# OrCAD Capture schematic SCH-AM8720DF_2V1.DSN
size Custom
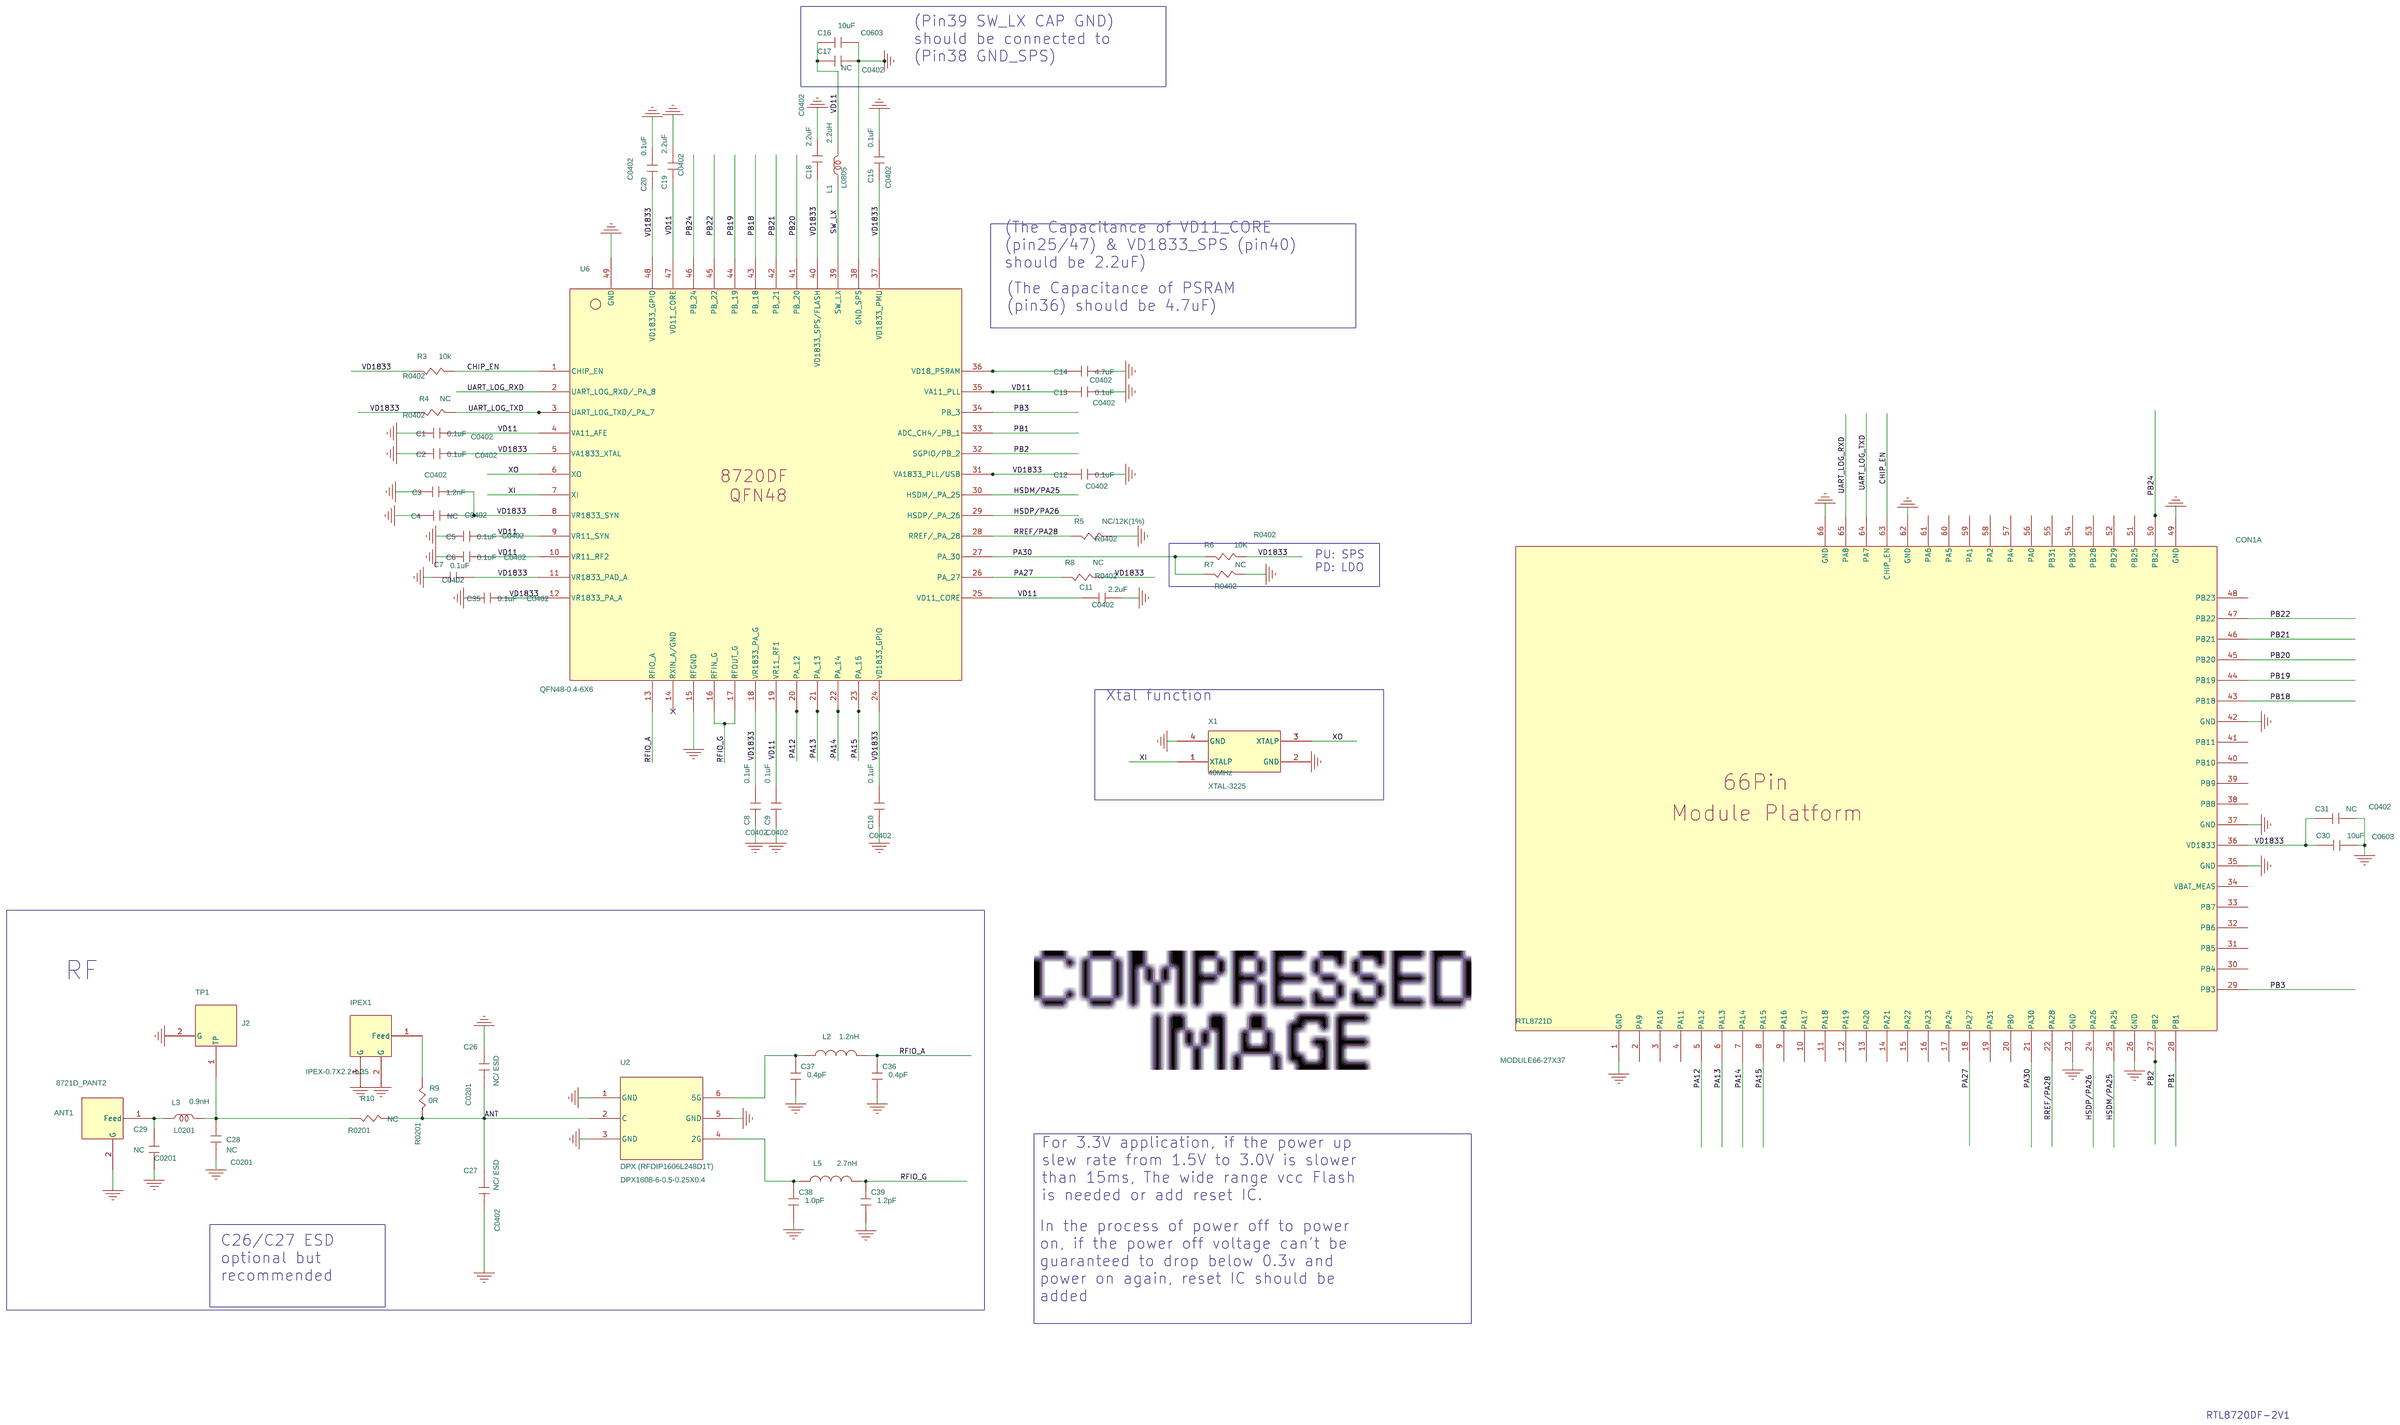
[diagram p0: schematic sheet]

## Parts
ANT1  TP  [8721D_PANT2]
C1  0.1uF  [C0402]
C2  0.1uF  [C0402]
C3  1.2nF  [C0402]
C4  NC  [C0402]
C5  0.1uF  [C0402]
C6  0.1uF  [C0402]
C7  0.1uF  [C0402]
C8  0.1uF  [C0402]
C9  0.1uF  [C0402]
C10  0.1uF  [C0402]
C11  2.2uF  [C0402]
C12  0.1uF  [C0402]
C13  0.1uF  [C0402]
C14  4.7uF  [C0402]
C15  0.1uF  [C0402]
C16  10uF  [C0603]
C17  NC  [C0402]
C18  2.2uF  [C0402]
C19  2.2uF  [C0402]
C20  0.1uF  [C0402]
C26  NC/ ESD  [C0201]
C27  NC/ ESD  [C0402]
C28  NC  [C0201]
C29  NC  [C0201]
C30  10uF  [C0603]
C31  NC  [C0402]
C35  0.1uF  [C0402]
C36  0.4pF  [C0402]
C37  0.4pF  [C0402]
C38  1.0pF  [C0402]
C39  1.2pF  [C0402]
CON1  RTL8721D  [MODULE66-27X37]  (section A)
IPEX1  TP  [IPEX-0.7X2.2-1.35]
L1  2.2uH  [L0805]
L2  1.2nH  [L0402]
L3  0.9nH  [L0201]
L5  2.7nH  [L0402]
R3  10k  [R0402]
R4  NC  [R0402]
R5  NC/12K(1%)  [R0402]
R6  10K  [R0402]
R7  NC  [R0402]
R8  NC  [R0402]
R9  0R  [R0201]
R10  NC  [R0201]
TP1  TP  [J2]
U2  DPX (RFDIP1606L248D1T)  [DPX1608-6-0.5-0.25X0.4]
U6  RL5760_001  [QFN48-0.4-6X6]
X1  40MHz  [XTAL-3225]

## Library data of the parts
ANT1 = TP_2
C1-C20 C26-C31 C35-C39 = C_402
CON1 = 8723BS_73
IPEX1 = TP_3
L1 L3 = L0402_1.7NH_ACX
L2 L5 = INDUCTOR: BRCMPN: RokuPN Checked; OPTION: RF; PartDesc: Inductor, 2.0nH, 5%, 0402, OBD; ROKUPN: 1372000247
R3-R10 = R0402_1.06K_WALSIN
TP1 = TP_4
U2 = 9346_19
U6 = RL5760_45
X1 = 9346_0

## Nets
GND: ANT1.2(G) C1.1 C2.1 C3.1 C4.2 C5.2 C6.2 C7.1 C8.2 C9.2 C10.2 C11.2 C12.2 C13.2 C14.2 C15.2 C16.1 C17.1 C18.2 C19.2 C20.2 C26.1 C27.2 C28.1 C29.1 C30.2 C31.1 C35.1 C36.2 C37.2 C38.2 C39.2 CON1.1(GND) CON1.23(GND) CON1.26(GND) CON1.35(GND) CON1.37(GND) CON1.42(GND) CON1.49(GND) CON1.62(GND) CON1.66(GND) IPEX1.2(G) IPEX1.3(G) R5.1 R7.2 TP1.2(G) U2.1(GND) U2.3(GND) U2.5(GND) U6.15(RFGND) U6.38(GND_SPS) U6.49(GND) X1.2(GND) X1.4(GND)
ANT: C26.2 C27.1 R9.1 R10.1 U2.2(C)
CHIP_EN: CON1.63(CHIP_EN) R3.1 U6.1(CHIP_EN)
HSDM/PA25: CON1.25(PA25) U6.30(HSDM/_PA_25)
HSDP/PA26: CON1.24(PA26) U6.29(HSDP/_PA_26)
PA12: CON1.5(PA12) U6.20(PA_12)
PA13: CON1.6(PA13) U6.21(PA_13)
PA14: CON1.7(PA14) U6.22(PA_14)
PA15: CON1.8(PA15) U6.23(PA_15)
PA27: CON1.18(PA27) R8.2 U6.26(PA_27)
PA30: CON1.21(PA30) R6.2 R7.1 U6.27(PA_30)
PB1: CON1.28(PB1) U6.33(ADC_CH4/_PB_1)
PB2: CON1.27(PB2) U6.32(SGPIO/PB_2)
PB3: CON1.29(PB3) U6.34(PB_3)
PB18: CON1.43(PB18) U6.43(PB_18)
PB19: CON1.44(PB19) U6.44(PB_19)
PB20: CON1.45(PB20) U6.41(PB_20)
PB21: CON1.46(PB21) U6.42(PB_21)
PB22: CON1.47(PB22) U6.45(PB_22)
PB24: CON1.50(PB24) U6.46(PB_24)
RFIO_A: C36.1 L2.2 U6.13(RFIO_A)
RFIO_G: C39.1 L5.2 U6.16(RFIN_G) U6.17(RFOUT_G)
RREF/PA28: CON1.22(PA28) R5.2 U6.28(RREF/_PA)
SW_LX: L1.1 U6.39(SW_LX)
UART_LOG_RXD: CON1.65(PA8) U6.2(UART_LOG_RXD/_PA_8)
UART_LOG_TXD: CON1.64(PA7) R4.1 U6.3(UART_LOG_TXD/_PA_7)
VD11: C1.2 C5.1 C6.1 C9.1 C11.1 C13.1 C16.2 C17.2 C19.1 L1.2 U6.4(VA11_AFE) U6.9(VR11_SYN) U6.10(VR11_RF2) U6.19(VR11_RF1) U6.25(VD11_CORE) U6.35(VA11_PLL) U6.47(VD11_CORE)
VD1833: C2.2 C3.2 C4.1 C7.2 C8.1 C10.1 C12.1 C15.1 C18.1 C20.1 C30.1 C31.2 C35.2 CON1.36(VD1833) R3.2 R4.2 R6.1 R8.1 U6.5(VA1833_XTAL) U6.8(VR1833_SYN) U6.11(VR1833_PAD_A) U6.12(VR1833_PA_A) U6.18(VR1833_PA_G) U6.24(VD1833_GPIO) U6.31(VA1833_PLL/USB) U6.37(VD1833_PMU) U6.40(VD1833_SPS/FLASH) U6.48(VD1833_GPIO)
XI: U6.7(XI) X1.1(XTALP)
XO: U6.6(XO) X1.3(XTALP)
N17891558: C14.1 U6.36(VD18_PSRAM)
N18284891: C28.2 L3.2 R10.2 TP1.1(TP)
N18284935: ANT1.1(Feed) C29.2 L3.1
N18284958: IPEX1.1(Feed) R9.2
N18284983: C38.1 L5.1 U2.4(2G)
N18284997: C37.1 L2.1 U2.6(5G)

Not connected (* = marked no-connect by the designer): CON1 2(PA9) 3(PA10) 4(PA11) 9(PA16) 10(PA17) 11(PA18) 12(PA19) 13(PA20) 14(PA21) 15(PA22) 16(PA23) 17(PA24) 19(PA31) 20(PB0) 30(PB4) 31(PB5) 32(PB6) 33(PB7) 34(VBAT_MEAS) 38(PB8) 39(PB9) 40(PB10) 41(PB11) 48(PB23) 51(PB25) 52(PB29) 53(PB28) 54(PB30) 55(PB31) 56(PA0) 57(PA4) 58(PA2) 59(PA1) 60(PA5) 61(PA6); U6 14(RXIN_A/GND)*

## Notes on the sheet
- (Pin39 SW_LX CAP GND)
  should be connected to
  (Pin38 GND_SPS)
- (The Capacitance of VD11_CORE
  (pin25/47) & VD1833_SPS (pin40)
  should be 2.2uF)
- (The Capacitance of PSRAM
  (pin36) should be 4.7uF)
- PU: SPS
  PD: LDO
- Xtal function
- RF
- For 3.3V application, if the power up
  slew rate from 1.5V to 3.0V is slower
  than 15ms, The wide range vcc Flash
  is needed or add reset IC.
- In the process of power off to power
  on, if the power off voltage can't be
  guaranteed to drop below 0.3v and
  power on again, reset IC should be
  added
- C26/C27 ESD
  optional but
  recommended
- RTL8720DF-2V1
